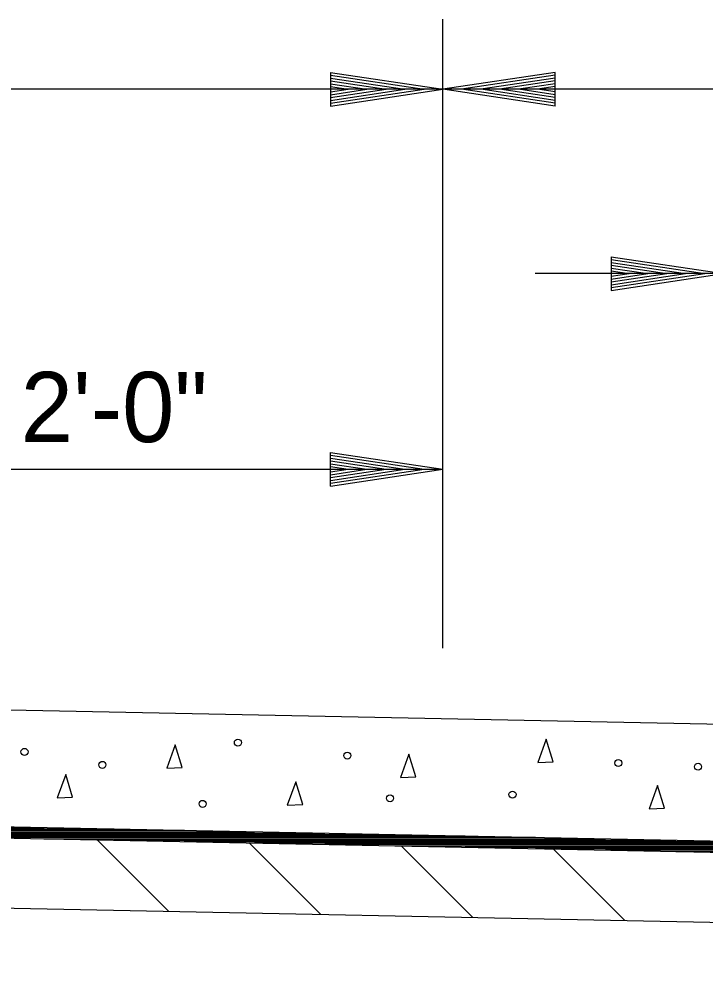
# Model space of a CAD drawing. Extents: x 60325 to 61047, y 53669 to 53767.
# Drawn here: x 60603.53 to 60608.41, y 53733.33 to 53740.09 of the extents above; entities that cross this region are included whole.
import ezdxf

# ---------------------------------------------------------------- set-up
doc = ezdxf.new("R2010")
doc.units = 0
doc.layers.add('R_Border', color=7, linetype='Continuous')
doc.layers.add('R_Border Prem', color=7, linetype='Continuous')

msp = doc.modelspace()

# ---------------------------------------------------------------- linework, layer by layer
at = {"layer": 'R_Border'}
for p, q in [((60606.5451, 53735.6112), (60606.5451, 53740.0912)), ((60605.7451, 53739.7112), (60606.5451, 53739.5912)), ((60605.7451, 53739.7112), (60605.7451, 53739.4712)), ((60605.7451, 53739.6912), (60606.4115, 53739.5912)), ((60605.7451, 53739.6708), (60606.2739, 53739.5912)), ((60605.7451, 53739.6508), (60606.1407, 53739.5912)), ((60605.7451, 53739.63), (60606.0051, 53739.5912)), ((60605.7451, 53739.61), (60605.8715, 53739.5912)), ((60606.5451, 53739.5912), (60594.5451, 53739.5912)), ((60605.7451, 53739.4712), (60606.5451, 53739.5912)), ((60605.7451, 53739.552), (60606.0051, 53739.5912)), ((60605.7451, 53739.5116), (60606.2739, 53739.5912)), ((60605.7451, 53739.4912), (60606.4115, 53739.5912)), ((60605.7451, 53739.5316), (60606.1407, 53739.5912)), ((60605.7451, 53739.5724), (60605.8715, 53739.5912)), ((60605.7451, 53737.0054), (60606.5451, 53736.8854)), ((60605.7451, 53736.7654), (60605.7451, 53737.0054)), ((60605.7451, 53736.9854), (60606.4115, 53736.8854)), ((60605.7451, 53736.965), (60606.2739, 53736.8854)), ((60605.7451, 53736.945), (60606.1407, 53736.8854)), ((60605.7451, 53736.9246), (60606.0051, 53736.8854)), ((60605.7451, 53736.9042), (60605.8715, 53736.8854)), ((60603.1984, 53736.8854), (60606.5451, 53736.8854)), ((60605.7451, 53736.7654), (60606.5451, 53736.8854)), ((60605.7451, 53736.8466), (60606.0051, 53736.8854)), ((60605.7451, 53736.8058), (60606.2739, 53736.8854)), ((60605.7451, 53736.7854), (60606.4115, 53736.8854)), ((60605.7451, 53736.8258), (60606.1407, 53736.8854)), ((60605.7451, 53736.8666), (60605.8715, 53736.8854))]:
    msp.add_line(p, q, dxfattribs=at)
msp.add_lwpolyline([(60580.5398, 53735.6358), (60582.5299, 53735.5922), (60608.5451, 53735.0712)], dxfattribs=at)
at = {"layer": 'R_Border Prem'}
for p, q in [((60607.3451, 53739.7112), (60606.5451, 53739.5912)), ((60607.3451, 53739.6912), (60606.6787, 53739.5912)), ((60607.3451, 53739.4712), (60607.3451, 53739.7112)), ((60607.3451, 53739.6708), (60606.8163, 53739.5912)), ((60607.3451, 53739.6508), (60606.9495, 53739.5912)), ((60607.3451, 53739.6304), (60607.0851, 53739.5912)), ((60607.3451, 53739.61), (60607.2187, 53739.5912)), ((60616.5451, 53739.5912), (60606.5451, 53739.5912)), ((60607.3451, 53739.4712), (60606.5451, 53739.5912)), ((60607.3451, 53739.4912), (60606.6787, 53739.5912)), ((60607.3451, 53739.5116), (60606.8163, 53739.5912)), ((60607.3451, 53739.5316), (60606.9495, 53739.5912)), ((60607.3451, 53739.5524), (60607.0851, 53739.5912)), ((60607.3451, 53739.5724), (60607.2187, 53739.5912)), ((60607.7451, 53738.3987), (60608.5451, 53738.2787)), ((60607.7451, 53738.3987), (60607.7451, 53738.1587)), ((60607.7451, 53738.3787), (60608.4115, 53738.2787)), ((60607.7451, 53738.3583), (60608.2739, 53738.2787)), ((60607.7451, 53738.3383), (60608.1407, 53738.2787)), ((60608.5451, 53738.2787), (60607.2028, 53738.2787)), ((60607.7451, 53738.3175), (60608.0051, 53738.2787)), ((60607.7451, 53738.2975), (60607.8715, 53738.2787)), ((60607.7451, 53738.1587), (60608.5451, 53738.2787)), ((60607.7451, 53738.2395), (60608.0051, 53738.2787)), ((60607.7451, 53738.1991), (60608.2739, 53738.2787)), ((60607.7451, 53738.1787), (60608.4115, 53738.2787)), ((60607.7451, 53738.2191), (60608.1407, 53738.2787)), ((60607.7451, 53738.2599), (60607.8715, 53738.2787)), ((60571.5451, 53734.9779), (60610.5451, 53734.1979)), ((60571.5451, 53734.8979), (60610.5451, 53734.1179)), ((60571.5451, 53734.3978), (60625.0911, 53733.3269)), ((60599.7042, 53734.3347), (60603.705, 53734.3347)), ((60600.2042, 53734.3247), (60604.205, 53734.3247)), ((60600.7042, 53734.3147), (60604.705, 53734.3147)), ((60601.2042, 53734.3047), (60605.205, 53734.3047)), ((60601.7042, 53734.2947), (60605.705, 53734.2947)), ((60602.2042, 53734.2847), (60606.205, 53734.2847)), ((60602.7042, 53734.2747), (60606.705, 53734.2747)), ((60603.2042, 53734.2647), (60607.205, 53734.2647)), ((60603.7042, 53734.2547), (60607.705, 53734.2547)), ((60604.0845, 53734.2471), (60604.5948, 53733.7368)), ((60604.2042, 53734.2447), (60608.205, 53734.2447)), ((60604.7042, 53734.2347), (60608.705, 53734.2347)), ((60605.1668, 53734.2255), (60605.6771, 53733.7152)), ((60605.2042, 53734.2247), (60609.205, 53734.2247)), ((60605.7042, 53734.2147), (60609.705, 53734.2147)), ((60606.2042, 53734.2047), (60610.205, 53734.2047)), ((60606.2491, 53734.2038), (60606.7594, 53733.6935)), ((60606.7042, 53734.1947), (60610.5451, 53734.1947)), ((60607.2042, 53734.1847), (60610.5451, 53734.1847)), ((60607.3314, 53734.1822), (60607.8417, 53733.6719)), ((60607.7042, 53734.1747), (60610.5451, 53734.1747)), ((60608.2042, 53734.1647), (60610.5451, 53734.1647))]:
    msp.add_line(p, q, dxfattribs=at)
for points in [[(60607.2822, 53734.9629), (60607.2217, 53734.7969), (60607.3317, 53734.8014), (60607.2822, 53734.9629)], [(60604.639, 53734.9232), (60604.5785, 53734.7572), (60604.6885, 53734.7617), (60604.639, 53734.9232)], [(60606.3042, 53734.8571), (60606.2437, 53734.6911), (60606.3537, 53734.6956), (60606.3042, 53734.8571)], [(60603.8593, 53734.7118), (60603.7988, 53734.5458), (60603.9088, 53734.5503), (60603.8593, 53734.7118)], [(60605.4981, 53734.6589), (60605.4376, 53734.4929), (60605.5476, 53734.4974), (60605.4981, 53734.6589)], [(60608.0752, 53734.6325), (60608.0147, 53734.4665), (60608.1247, 53734.471), (60608.0752, 53734.6325)]]:
    msp.add_lwpolyline(points, dxfattribs=at)
for centre in [(60605.0856, 53734.9389), (60603.5658, 53734.8728), (60605.8653, 53734.8464), (60607.7949, 53734.7935), (60604.1208, 53734.7803), (60608.3631, 53734.7671), (60606.1693, 53734.5424), (60607.0416, 53734.5688), (60604.8345, 53734.5027)]:
    msp.add_circle(centre, 0.025, dxfattribs=at)

# ---------------------------------------------------------------- texts
at = {"layer": 'R_Border'}
msp.add_text('2\'-0"', height=0.5, dxfattribs=at).set_placement((60603.5391, 53737.0786))

doc.saveas('drawing.dxf')
